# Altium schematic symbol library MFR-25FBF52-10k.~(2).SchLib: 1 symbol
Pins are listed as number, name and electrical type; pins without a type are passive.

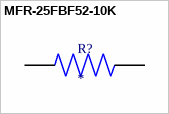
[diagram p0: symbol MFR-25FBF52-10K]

## MFR-25FBF52-10K
designator R?
10.2 kOhms Â±1% 0.25W, 1/4W Through Hole Resistor Axial - Metal Film; MF: Yageo; MP: MFR-25FBF52-10K
footprint RESAD1100W55L680D260
pins: 1, 2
